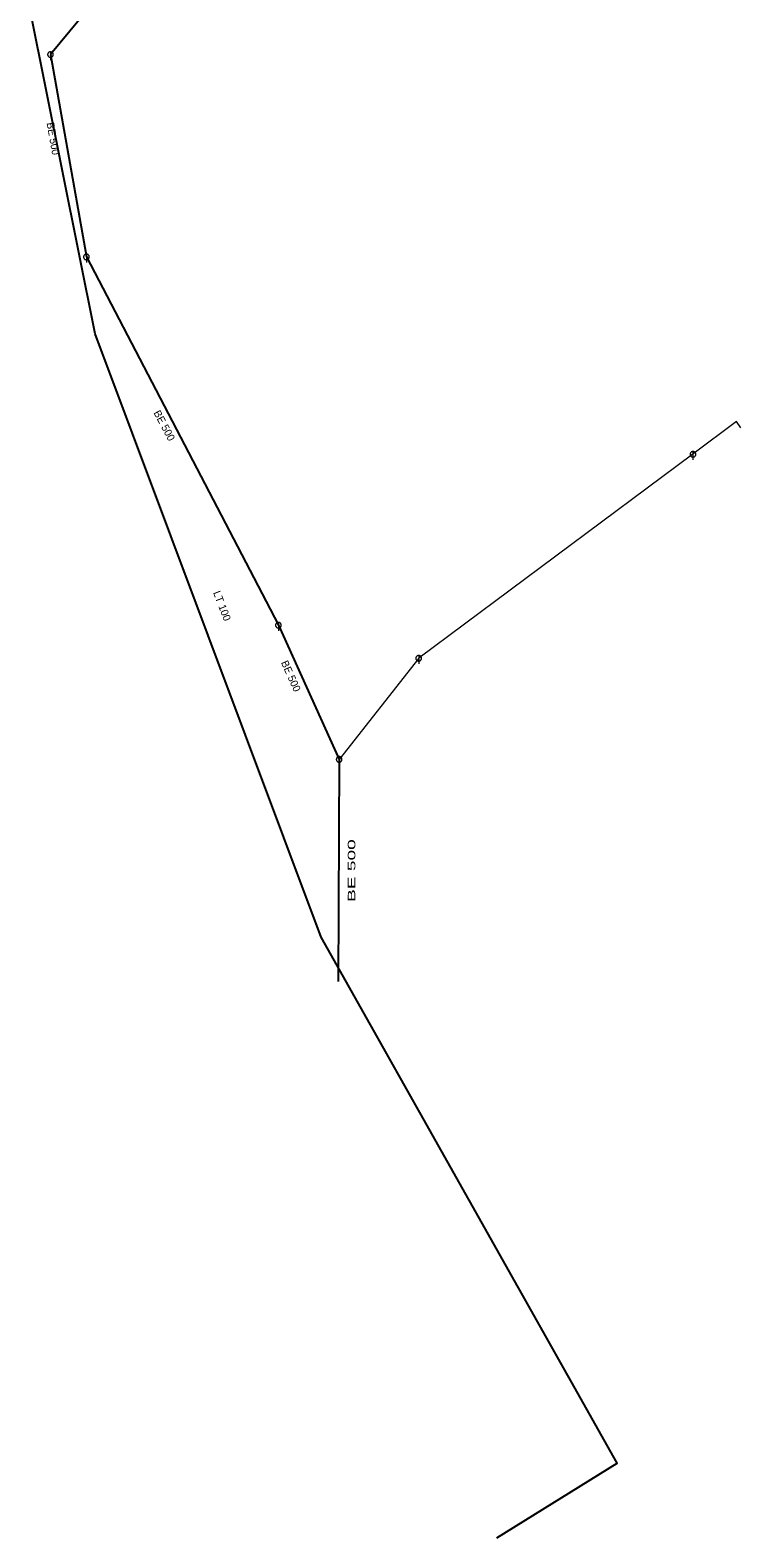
# Model space of a CAD drawing. Extents: x -687515 to -686506, y -974029 to -973461.
# Drawn here: x -687165.8 to -687102.7, y -974028.6 to -973894.7 of the extents above; entities that cross this region are included whole.
import ezdxf
from ezdxf.enums import TextEntityAlignment as Align

# ---------------------------------------------------------------- set-up
doc = ezdxf.new("R2010")
doc.units = 0
doc.header["$LTSCALE"] = 0.27
for name, color, linetype, lineweight in [('1', 7, 'Continuous', 13), ('11', 7, 'Continuous', 13), ('14', 7, 'Continuous', 25), ('17', 7, 'Continuous', 25), ('22', 7, 'Continuous', 13)]:
    doc.layers.add(name, color=color, linetype=linetype, lineweight=lineweight)

msp = doc.modelspace()

# ---------------------------------------------------------------- linework, layer by layer
at = {"layer": '11'}
for p, q in [((-687106.99, -973932.4), (-687131.34, -973950.51)), ((-687131.34, -973950.51), (-687138.399, -973959.489))]:
    msp.add_line(p, q, dxfattribs=at)
msp.add_lwpolyline([(-687102.74, -973930.05), (-687103.13, -973929.48), (-687106.99, -973932.4)], dxfattribs=at)
at = {"layer": '14'}
for p, q in [((-687149.333, -973879.12), (-687164.024, -973896.907)), ((-687164.024, -973896.907), (-687160.836, -973914.878)), ((-687160.836, -973914.878), (-687143.793, -973947.573)), ((-687143.793, -973947.573), (-687138.399, -973959.489)), ((-687138.399, -973959.489), (-687138.481, -973979.218))]:
    msp.add_line(p, q, dxfattribs=at)
at = {"layer": '17'}
msp.add_lwpolyline([(-687124.395, -974028.598), (-687113.714, -974021.973), (-687139.989, -973975.271), (-687160.068, -973921.704), (-687165.829, -973892.978), (-687149.548, -973877.175), (-687105.661, -973883.258)], dxfattribs=at)
at = {"layer": '22'}
for p, q in [((-687164.023, -973896.655), (-687164.024, -973897.399)), ((-687160.835, -973914.626), (-687160.836, -973915.37)), ((-687106.989, -973932.148), (-687106.99, -973932.892)), ((-687143.792, -973947.321), (-687143.793, -973948.065)), ((-687131.339, -973950.258), (-687131.34, -973951.002)), ((-687138.398, -973959.237), (-687138.399, -973959.98))]:
    msp.add_line(p, q, dxfattribs=at)
for points in [[(-687163.772, -973896.907), (-687163.773, -973896.881), (-687163.777, -973896.855), (-687163.783, -973896.829), (-687163.793, -973896.805), (-687163.805, -973896.781), (-687163.819, -973896.759), (-687163.836, -973896.738), (-687163.854, -973896.72), (-687163.875, -973896.703), (-687163.897, -973896.689), (-687163.921, -973896.677), (-687163.945, -973896.667), (-687163.971, -973896.661), (-687163.997, -973896.657), (-687164.023, -973896.655), (-687164.049, -973896.656), (-687164.075, -973896.66), (-687164.101, -973896.666), (-687164.126, -973896.676), (-687164.149, -973896.688), (-687164.171, -973896.702), (-687164.192, -973896.719), (-687164.21, -973896.737), (-687164.227, -973896.758), (-687164.241, -973896.78), (-687164.253, -973896.804), (-687164.263, -973896.828), (-687164.27, -973896.854), (-687164.274, -973896.88), (-687164.276, -973896.906), (-687164.275, -973896.932), (-687164.271, -973896.958), (-687164.264, -973896.984), (-687164.254, -973897.009), (-687164.242, -973897.032), (-687164.228, -973897.054), (-687164.211, -973897.075), (-687164.193, -973897.093), (-687164.172, -973897.11), (-687164.15, -973897.124), (-687164.127, -973897.136), (-687164.102, -973897.146), (-687164.076, -973897.153), (-687164.05, -973897.157), (-687164.024, -973897.159), (-687163.998, -973897.158), (-687163.972, -973897.154), (-687163.946, -973897.147), (-687163.922, -973897.137), (-687163.898, -973897.125), (-687163.876, -973897.111), (-687163.855, -973897.094), (-687163.837, -973897.076), (-687163.82, -973897.055), (-687163.806, -973897.033), (-687163.794, -973897.01), (-687163.784, -973896.985), (-687163.778, -973896.959), (-687163.774, -973896.933)], [(-687160.584, -973914.878), (-687160.585, -973914.852), (-687160.589, -973914.826), (-687160.595, -973914.8), (-687160.605, -973914.776), (-687160.617, -973914.752), (-687160.631, -973914.73), (-687160.648, -973914.709), (-687160.666, -973914.691), (-687160.687, -973914.674), (-687160.709, -973914.66), (-687160.733, -973914.648), (-687160.757, -973914.638), (-687160.783, -973914.632), (-687160.809, -973914.628), (-687160.835, -973914.626), (-687160.861, -973914.627), (-687160.887, -973914.631), (-687160.913, -973914.637), (-687160.938, -973914.647), (-687160.961, -973914.659), (-687160.983, -973914.673), (-687161.004, -973914.69), (-687161.022, -973914.708), (-687161.039, -973914.729), (-687161.053, -973914.751), (-687161.065, -973914.775), (-687161.075, -973914.799), (-687161.082, -973914.825), (-687161.086, -973914.851), (-687161.088, -973914.877), (-687161.087, -973914.903), (-687161.083, -973914.929), (-687161.076, -973914.955), (-687161.066, -973914.98), (-687161.054, -973915.003), (-687161.04, -973915.025), (-687161.023, -973915.046), (-687161.005, -973915.064), (-687160.984, -973915.081), (-687160.962, -973915.095), (-687160.939, -973915.107), (-687160.914, -973915.117), (-687160.888, -973915.124), (-687160.862, -973915.128), (-687160.836, -973915.13), (-687160.81, -973915.129), (-687160.784, -973915.125), (-687160.758, -973915.118), (-687160.734, -973915.108), (-687160.71, -973915.096), (-687160.688, -973915.082), (-687160.667, -973915.065), (-687160.649, -973915.047), (-687160.632, -973915.026), (-687160.618, -973915.004), (-687160.606, -973914.981), (-687160.596, -973914.956), (-687160.59, -973914.93), (-687160.586, -973914.904)], [(-687106.738, -973932.4), (-687106.739, -973932.374), (-687106.743, -973932.348), (-687106.749, -973932.322), (-687106.759, -973932.298), (-687106.771, -973932.274), (-687106.785, -973932.252), (-687106.802, -973932.231), (-687106.82, -973932.213), (-687106.841, -973932.196), (-687106.863, -973932.182), (-687106.887, -973932.17), (-687106.911, -973932.16), (-687106.937, -973932.154), (-687106.963, -973932.15), (-687106.989, -973932.148), (-687107.015, -973932.149), (-687107.041, -973932.153), (-687107.067, -973932.159), (-687107.092, -973932.169), (-687107.115, -973932.181), (-687107.137, -973932.195), (-687107.158, -973932.212), (-687107.176, -973932.23), (-687107.193, -973932.251), (-687107.207, -973932.273), (-687107.219, -973932.297), (-687107.229, -973932.321), (-687107.236, -973932.347), (-687107.24, -973932.373), (-687107.242, -973932.399), (-687107.241, -973932.425), (-687107.237, -973932.451), (-687107.23, -973932.477), (-687107.22, -973932.502), (-687107.208, -973932.525), (-687107.194, -973932.547), (-687107.177, -973932.568), (-687107.159, -973932.586), (-687107.138, -973932.603), (-687107.116, -973932.617), (-687107.093, -973932.629), (-687107.068, -973932.639), (-687107.042, -973932.646), (-687107.016, -973932.65), (-687106.99, -973932.652), (-687106.964, -973932.651), (-687106.938, -973932.647), (-687106.912, -973932.64), (-687106.888, -973932.63), (-687106.864, -973932.618), (-687106.842, -973932.604), (-687106.821, -973932.587), (-687106.803, -973932.569), (-687106.786, -973932.548), (-687106.772, -973932.526), (-687106.76, -973932.503), (-687106.75, -973932.478), (-687106.744, -973932.452), (-687106.74, -973932.426)], [(-687143.541, -973947.573), (-687143.542, -973947.547), (-687143.546, -973947.521), (-687143.552, -973947.495), (-687143.562, -973947.471), (-687143.574, -973947.447), (-687143.588, -973947.425), (-687143.605, -973947.404), (-687143.623, -973947.386), (-687143.644, -973947.369), (-687143.666, -973947.355), (-687143.69, -973947.343), (-687143.714, -973947.333), (-687143.74, -973947.327), (-687143.766, -973947.323), (-687143.792, -973947.321), (-687143.818, -973947.322), (-687143.844, -973947.326), (-687143.87, -973947.332), (-687143.895, -973947.342), (-687143.918, -973947.354), (-687143.94, -973947.368), (-687143.961, -973947.385), (-687143.979, -973947.403), (-687143.996, -973947.424), (-687144.01, -973947.446), (-687144.022, -973947.47), (-687144.032, -973947.494), (-687144.039, -973947.52), (-687144.043, -973947.546), (-687144.044, -973947.572), (-687144.044, -973947.598), (-687144.04, -973947.624), (-687144.033, -973947.65), (-687144.023, -973947.675), (-687144.011, -973947.698), (-687143.997, -973947.72), (-687143.98, -973947.741), (-687143.962, -973947.759), (-687143.941, -973947.776), (-687143.919, -973947.79), (-687143.896, -973947.802), (-687143.871, -973947.812), (-687143.845, -973947.819), (-687143.819, -973947.823), (-687143.793, -973947.825), (-687143.767, -973947.824), (-687143.741, -973947.82), (-687143.715, -973947.813), (-687143.691, -973947.803), (-687143.667, -973947.791), (-687143.645, -973947.777), (-687143.624, -973947.76), (-687143.606, -973947.742), (-687143.589, -973947.721), (-687143.575, -973947.699), (-687143.563, -973947.676), (-687143.553, -973947.651), (-687143.547, -973947.625), (-687143.543, -973947.599)], [(-687131.088, -973950.51), (-687131.089, -973950.484), (-687131.093, -973950.458), (-687131.099, -973950.432), (-687131.109, -973950.408), (-687131.121, -973950.384), (-687131.135, -973950.362), (-687131.152, -973950.341), (-687131.17, -973950.323), (-687131.191, -973950.306), (-687131.213, -973950.292), (-687131.237, -973950.28), (-687131.261, -973950.27), (-687131.287, -973950.264), (-687131.313, -973950.26), (-687131.339, -973950.258), (-687131.365, -973950.259), (-687131.391, -973950.263), (-687131.417, -973950.269), (-687131.442, -973950.279), (-687131.465, -973950.291), (-687131.487, -973950.305), (-687131.508, -973950.322), (-687131.526, -973950.34), (-687131.543, -973950.361), (-687131.557, -973950.383), (-687131.569, -973950.407), (-687131.579, -973950.431), (-687131.586, -973950.457), (-687131.59, -973950.483), (-687131.592, -973950.509), (-687131.591, -973950.535), (-687131.587, -973950.561), (-687131.58, -973950.587), (-687131.57, -973950.612), (-687131.558, -973950.635), (-687131.544, -973950.657), (-687131.527, -973950.678), (-687131.509, -973950.696), (-687131.488, -973950.713), (-687131.466, -973950.727), (-687131.443, -973950.739), (-687131.418, -973950.749), (-687131.392, -973950.756), (-687131.366, -973950.76), (-687131.34, -973950.762), (-687131.314, -973950.761), (-687131.288, -973950.757), (-687131.262, -973950.75), (-687131.238, -973950.74), (-687131.214, -973950.728), (-687131.192, -973950.714), (-687131.171, -973950.697), (-687131.153, -973950.679), (-687131.136, -973950.658), (-687131.122, -973950.636), (-687131.11, -973950.613), (-687131.1, -973950.588), (-687131.094, -973950.562), (-687131.09, -973950.536)], [(-687138.147, -973959.489), (-687138.148, -973959.463), (-687138.152, -973959.437), (-687138.158, -973959.411), (-687138.168, -973959.387), (-687138.18, -973959.363), (-687138.194, -973959.341), (-687138.211, -973959.32), (-687138.229, -973959.302), (-687138.25, -973959.285), (-687138.272, -973959.271), (-687138.296, -973959.259), (-687138.32, -973959.249), (-687138.346, -973959.243), (-687138.372, -973959.239), (-687138.398, -973959.237), (-687138.424, -973959.238), (-687138.45, -973959.242), (-687138.476, -973959.248), (-687138.501, -973959.258), (-687138.524, -973959.27), (-687138.546, -973959.284), (-687138.567, -973959.301), (-687138.585, -973959.319), (-687138.602, -973959.34), (-687138.616, -973959.362), (-687138.628, -973959.386), (-687138.638, -973959.41), (-687138.645, -973959.436), (-687138.649, -973959.462), (-687138.651, -973959.488), (-687138.65, -973959.514), (-687138.646, -973959.54), (-687138.639, -973959.566), (-687138.629, -973959.591), (-687138.617, -973959.614), (-687138.603, -973959.636), (-687138.586, -973959.657), (-687138.568, -973959.675), (-687138.547, -973959.692), (-687138.525, -973959.706), (-687138.502, -973959.718), (-687138.477, -973959.728), (-687138.451, -973959.735), (-687138.425, -973959.739), (-687138.399, -973959.74), (-687138.373, -973959.74), (-687138.347, -973959.736), (-687138.321, -973959.729), (-687138.297, -973959.719), (-687138.273, -973959.707), (-687138.251, -973959.693), (-687138.23, -973959.676), (-687138.212, -973959.658), (-687138.195, -973959.637), (-687138.181, -973959.615), (-687138.169, -973959.592), (-687138.159, -973959.567), (-687138.153, -973959.541), (-687138.149, -973959.515)]]:
    msp.add_lwpolyline(points, close=True, dxfattribs=at)

# ---------------------------------------------------------------- texts
at = {"layer": '1'}
for s, rotation, p in [('BE 500', 280, (-687164.118, -973904.429)), ('BE 500', 298, (-687154.211, -973930.004)), ('LT 100', 291, (-687149.101, -973945.974)), ('BE 500', 294, (-687142.983, -973952.223))]:
    msp.add_text(s, height=0.6667, rotation=rotation, dxfattribs=at).set_placement(p, align=Align.CENTER)
at = {"layer": '1', "width": 1.9}
msp.add_text('BE 500', height=0.6667, rotation=90, dxfattribs=at).set_placement((-687136.966, -973969.359), align=Align.CENTER)

doc.saveas('drawing.dxf')
